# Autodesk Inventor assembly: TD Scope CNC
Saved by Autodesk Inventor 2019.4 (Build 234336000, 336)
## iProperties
Created: 2020-09
Part Number: TD Scope CNC
Document SubType Name: Assembly
Designer: Administrator
Title: TD Scope CNC v50
Author: Administrator
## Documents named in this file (9)
- c:\worker\convert-fusion-r07\tmp\job-1\5\output\files\8dd25ce2-84a7-4226-b30d-3ab8d8153af1\553bcda0-c476-4495-855f-81b91929ed78.iam
- c:\worker\convert-fusion-r07\tmp\job-1\5\output\files\8dd25ce2-84a7-4226-b30d-3ab8d8153af1\Tube.ipt
- c:\worker\convert-fusion-r07\tmp\job-1\5\output\files\8dd25ce2-84a7-4226-b30d-3ab8d8153af1\Lens.ipt
- c:\worker\convert-fusion-r07\tmp\job-1\5\output\files\8dd25ce2-84a7-4226-b30d-3ab8d8153af1\Front Lens Holder.ipt
- c:\worker\convert-fusion-r07\tmp\job-1\5\output\files\8dd25ce2-84a7-4226-b30d-3ab8d8153af1\Front Lens Spacer.ipt
- c:\worker\convert-fusion-r07\tmp\job-1\5\output\files\8dd25ce2-84a7-4226-b30d-3ab8d8153af1\Rear Mount.ipt
- c:\worker\convert-fusion-r07\tmp\job-1\5\output\files\8dd25ce2-84a7-4226-b30d-3ab8d8153af1\Light Stop.ipt
- c:\worker\convert-fusion-r07\tmp\job-1\5\output\files\8dd25ce2-84a7-4226-b30d-3ab8d8153af1\Eyepiece Tube.ipt
- c:\worker\convert-fusion-r07\tmp\job-1\5\output\files\8dd25ce2-84a7-4226-b30d-3ab8d8153af1\Eyepiece.ipt
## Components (8 placed, 8 different names)
1. Tube:1
2. Lens:1
3. Front Lens Holder:1
4. Front Lens Spacer:1
5. Rear Mount:1
6. Light Stop:1
7. Eyepiece Tube:1
8. Eyepiece:1
